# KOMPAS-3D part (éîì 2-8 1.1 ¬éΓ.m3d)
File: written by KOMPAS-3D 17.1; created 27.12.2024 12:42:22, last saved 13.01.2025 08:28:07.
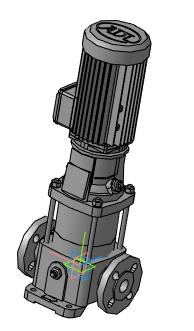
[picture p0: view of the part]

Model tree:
1. Операция без истории:4  (labels: ВМН 2-8 1.1 кВт)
